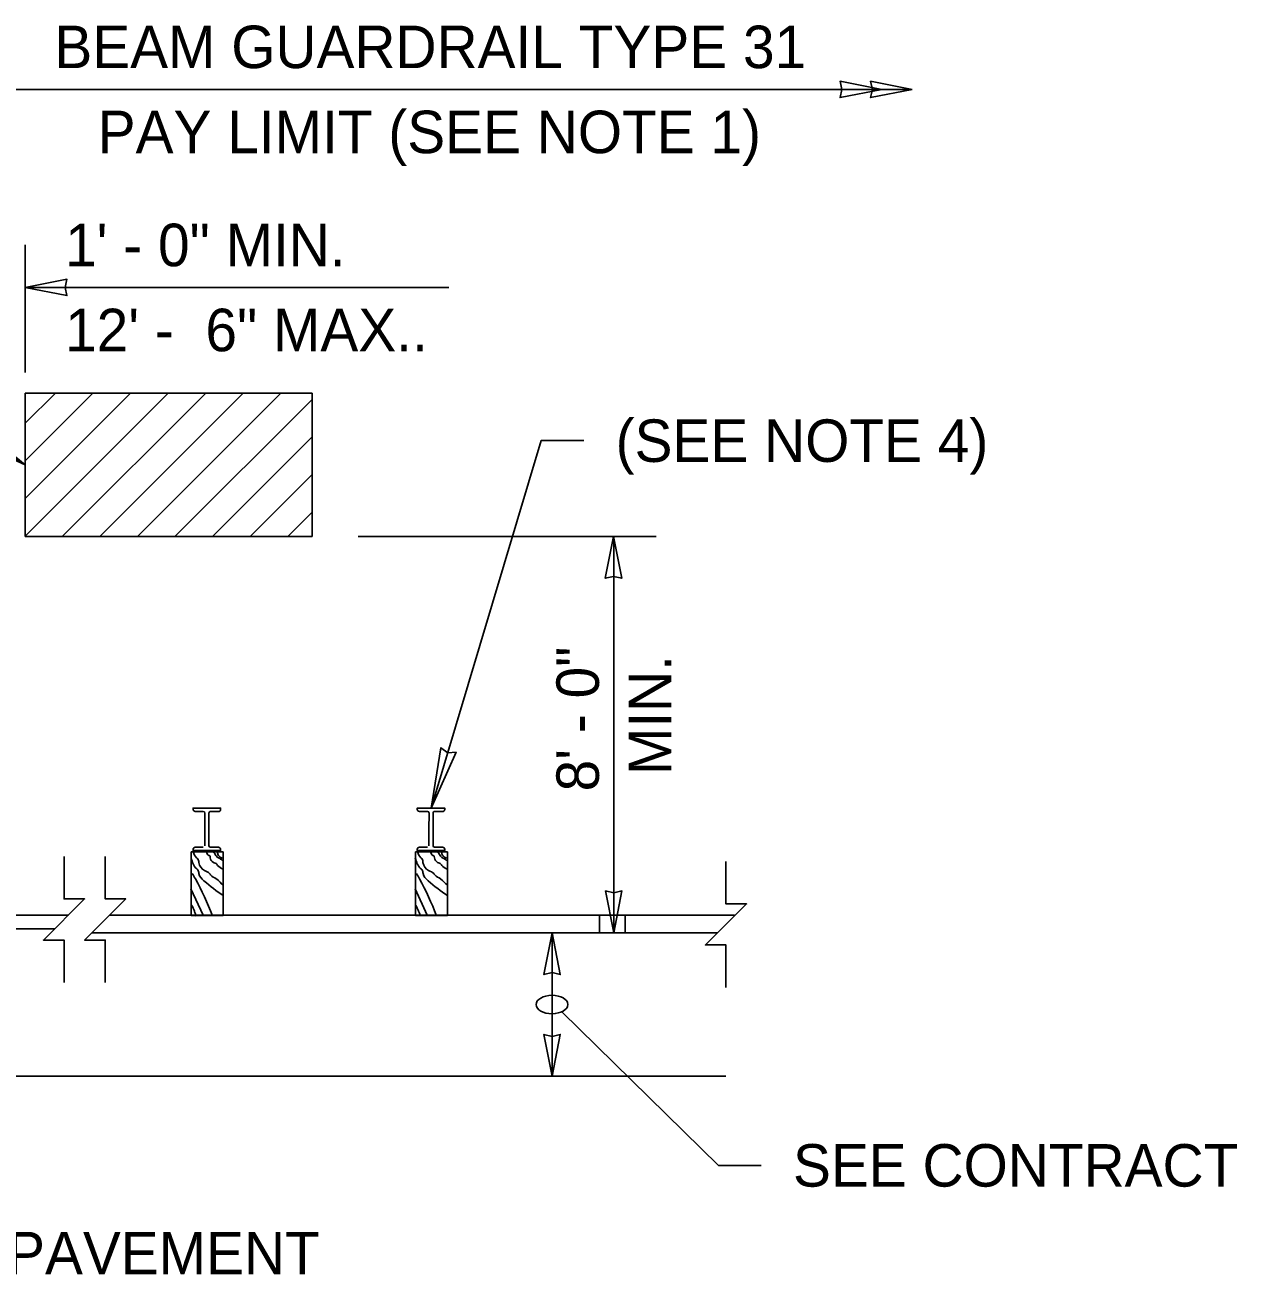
# Model space of a CAD drawing. Extents: x 99862 to 103680, y 99470 to 102076.
# Drawn here: x 100949.2 to 101405.4, y 100910.7 to 101381.1 of the extents above; entities that cross this region are included whole.
import ezdxf

# ---------------------------------------------------------------- set-up
doc = ezdxf.new("R2010")
doc.units = 0
for name, color, linetype in [('Level 1', 7, 'Continuous'), ('Level 10', 7, 'Continuous'), ('Level 13', 7, 'Continuous'), ('Level 15', 7, 'Continuous'), ('Level 17', 7, 'Continuous'), ('Level 2', 7, 'Continuous'), ('Level 20', 7, 'Continuous'), ('Level 21', 7, 'Continuous'), ('Level 4', 7, 'Continuous'), ('Level 9', 7, 'Continuous')]:
    doc.layers.add(name, color=color, linetype=linetype)

msp = doc.modelspace()

# ---------------------------------------------------------------- linework, layer by layer
at = {"layer": 'Level 1'}
for p, q in [((101216.27, 101046.07), (100981.02, 101046.07)), ((101165.38, 101046.07), (101165.38, 101039.46)), ((101175.15, 101046.07), (101175.15, 101039.46)), ((101209.66, 101039.46), (100974.41, 101039.46))]:
    msp.add_line(p, q, dxfattribs=at)
at = {"layer": 'Level 10'}
for p, q in [((101011.78, 101069.95), (101023.78, 101069.95)), ((101011.78, 101069.95), (101011.78, 101045.95)), ((101023.78, 101045.95), (101023.78, 101069.95)), ((101096.16, 101069.95), (101108.16, 101069.95)), ((101096.16, 101069.95), (101096.16, 101045.95)), ((101108.16, 101045.95), (101108.16, 101069.95)), ((101011.78, 101045.95), (101023.78, 101045.95)), ((101016.84, 101045.86), (101016.84, 101045.95)), ((101016.84, 101045.86), (101016.84, 101045.95)), ((101018.72, 101045.95), (101018.72, 101045.86)), ((101018.72, 101045.95), (101018.72, 101045.86)), ((101096.16, 101045.95), (101108.16, 101045.95)), ((101101.22, 101045.86), (101101.22, 101045.95)), ((101101.22, 101045.86), (101101.22, 101045.95)), ((101103.09, 101045.95), (101103.09, 101045.86)), ((101103.09, 101045.95), (101103.09, 101045.86))]:
    msp.add_line(p, q, dxfattribs=at)
at = {"layer": 'Level 13'}
for p, q in [((101011.66, 101056.04), (101016.25, 101046.03)), ((101096.03, 101056.04), (101100.63, 101046.03))]:
    msp.add_line(p, q, dxfattribs=at)
for points in [[(101012.54, 101069.94), (101013.81, 101067.66), (101014.26, 101067.25), (101014.62, 101065.86), (101016.74, 101062.84), (101018.65, 101061.75), (101019.06, 101061.21), (101021.2, 101059.76), (101021.38, 101059.62), (101023.8, 101057.34)], [(101017.51, 101069.94), (101018.32, 101068.58), (101018.72, 101068.42), (101018.89, 101067.7), (101020.13, 101065.93), (101021.37, 101065.28), (101021.7, 101064.84), (101023.76, 101063.43)], [(101020.2, 101069.95), (101020.62, 101069.26), (101021.52, 101067.98), (101022.51, 101067.38), (101023.68, 101066.65)], [(101021.62, 101069.92), (101021.97, 101068.6), (101023.68, 101067.48)], [(101096.91, 101069.94), (101098.19, 101067.66), (101098.64, 101067.25), (101098.99, 101065.86), (101101.12, 101062.84), (101103.03, 101061.75), (101103.44, 101061.21), (101105.57, 101059.76), (101105.75, 101059.62), (101108.17, 101057.34)], [(101101.88, 101069.94), (101102.7, 101068.58), (101103.1, 101068.42), (101103.27, 101067.7), (101104.51, 101065.93), (101105.75, 101065.28), (101106.07, 101064.84), (101108.13, 101063.43)], [(101104.58, 101069.95), (101104.99, 101069.26), (101105.9, 101067.98), (101106.89, 101067.38), (101108.06, 101066.65)], [(101105.99, 101069.92), (101106.35, 101068.6), (101108.06, 101067.48)], [(101011.72, 101067.68), (101013.82, 101063.54), (101014.27, 101063.13), (101014.63, 101061.74), (101016.57, 101059.02), (101023.78, 101053.43)], [(101096.1, 101067.68), (101098.2, 101063.54), (101098.65, 101063.13), (101099, 101061.74), (101100.95, 101059.02), (101108.16, 101053.43)], [(101012.18, 101061.82), (101013.33, 101059.81), (101019.75, 101045.89)], [(101096.56, 101061.82), (101097.71, 101059.81), (101104.12, 101045.89)], [(101011.76, 101050.11), (101011.91, 101049.85), (101012.06, 101049.59), (101012.33, 101049.05), (101012.82, 101047.94), (101013.28, 101046.81), (101013.51, 101046.24), (101013.75, 101045.69)], [(101096.14, 101050.11), (101096.29, 101049.85), (101096.43, 101049.59), (101096.71, 101049.05), (101097.19, 101047.94), (101097.65, 101046.81), (101097.88, 101046.24), (101098.12, 101045.69)]]:
    msp.add_spline(points, degree=3, dxfattribs=at)
at = {"layer": 'Level 15'}
for p, q in [((100949.27, 101215.58), (100837.28, 101282.31)), ((101102.03, 101086.38), (101143.51, 101224.66)), ((101159.51, 101224.66), (101143.51, 101224.66)), ((101170.81, 101039.46), (101170.81, 101188.58)), ((101147.56, 100985.46), (101147.56, 101039.46)), ((101210.25, 100951.93), (101151.24, 101009.72)), ((101226.25, 100951.93), (101210.25, 100951.93))]:
    msp.add_line(p, q, dxfattribs=at)
for points in [[(100949.27, 101215.58), (100931.42, 101230.12), (100930.75, 101227.03), (100928.28, 101225.04)], [(101102.03, 101086.38), (101105.73, 101109.1), (101108.29, 101107.23), (101111.45, 101107.39)], [(101170.81, 101039.46), (101167.72, 101055.19), (101170.81, 101054.46), (101173.89, 101055.19)], [(101147.56, 101039.46), (101144.48, 101023.74), (101147.56, 101024.47), (101150.65, 101023.74)], [(101147.56, 100985.46), (101144.48, 101001.19), (101147.56, 101000.46), (101150.65, 101001.19)]]:
    msp.add_lwpolyline(points, close=True, dxfattribs=at)
for points in [[(100963.91, 101068.19), (100963.91, 101052.19), (100971.65, 101052.19), (100956.16, 101036.7), (100963.91, 101036.7), (100963.91, 101020.7)], [(100979.39, 101068.19), (100979.39, 101052.19), (100987.14, 101052.19), (100971.65, 101036.7), (100979.39, 101036.7), (100979.39, 101020.7)], [(101213.04, 101066.35), (101213.04, 101050.35), (101220.79, 101050.35), (101205.3, 101034.87), (101213.04, 101034.87), (101213.04, 101018.87)]]:
    msp.add_lwpolyline(points, dxfattribs=at)
msp.add_ellipse((101147.56, 101012.46), major_axis=(6, 0.02), ratio=0.57735, dxfattribs=at)
at = {"layer": 'Level 17'}
for p, q in [((100949.27, 101188.58), (100949.27, 101242.58)), ((101057.27, 101242.58), (100949.27, 101242.58)), ((100949.27, 101231.21), (100960.65, 101242.58)), ((100949.27, 101217.07), (100974.79, 101242.58)), ((100949.27, 101202.92), (100988.93, 101242.58)), ((100949.27, 101188.78), (101003.07, 101242.58)), ((100963.21, 101188.58), (101017.21, 101242.58)), ((100977.36, 101188.58), (101031.36, 101242.58)), ((100991.5, 101188.58), (101045.5, 101242.58)), ((101057.27, 101188.58), (101057.27, 101242.58)), ((101005.64, 101188.58), (101057.27, 101240.21)), ((101019.78, 101188.58), (101057.27, 101226.07)), ((101033.92, 101188.58), (101057.27, 101211.93)), ((101048.07, 101188.58), (101057.27, 101197.79)), ((101057.27, 101188.58), (100949.27, 101188.58))]:
    msp.add_line(p, q, dxfattribs=at)
at = {"layer": 'Level 2'}
for p, q in [((100965.53, 101046.07), (100735.54, 101046.07)), ((100960.44, 101040.98), (100754.27, 101040.98))]:
    msp.add_line(p, q, dxfattribs=at)
at = {"layer": 'Level 20'}
for p, q in [((100933.41, 101356.85), (101283.16, 101356.85)), ((100949.27, 101250.31), (100949.27, 101298.31)), ((100949.27, 101282.31), (101108.71, 101282.31)), ((101074.61, 101188.58), (101186.7, 101188.58))]:
    msp.add_line(p, q, dxfattribs=at)
for points in [[(101271.67, 101356.85), (101255.95, 101353.77), (101256.67, 101356.85), (101255.95, 101359.94)], [(101283.16, 101356.85), (101267.44, 101353.77), (101268.17, 101356.85), (101267.44, 101359.94)], [(100949.27, 101282.31), (100965, 101279.23), (100964.27, 101282.31), (100965, 101285.39)], [(101170.7, 101188.58), (101167.62, 101172.86), (101170.7, 101173.58), (101173.79, 101172.86)]]:
    msp.add_lwpolyline(points, close=True, dxfattribs=at)
at = {"layer": 'Level 21'}
msp.add_line((101213.04, 100985.46), (100717.77, 100985.46), dxfattribs=at)
at = {"layer": 'Level 4'}
msp.add_line((101013.28, 101045.95), (101022.28, 101045.95), dxfattribs=at)
at = {"layer": 'Level 9'}
for p, q in [((101016.88, 101084.52), (101016.88, 101078.38)), ((101018.42, 101078.38), (101018.43, 101084.51)), ((101101.26, 101084.52), (101101.25, 101078.38)), ((101102.79, 101078.38), (101102.8, 101084.51)), ((101016.88, 101078.38), (101016.87, 101072.24)), ((101018.41, 101072.24), (101018.42, 101078.38)), ((101101.25, 101078.38), (101101.24, 101072.24)), ((101102.79, 101072.24), (101102.79, 101078.38))]:
    msp.add_line(p, q, dxfattribs=at)
for points in [[(101017.66, 101086.38), (101012.49, 101086.38), (101012.49, 101085.9)], [(101013.27, 101085.11), (101016.29, 101085.11)], [(101022.83, 101085.89), (101022.83, 101086.37), (101017.66, 101086.38)], [(101019.02, 101085.1), (101022.04, 101085.1)], [(101102.03, 101086.38), (101096.86, 101086.38), (101096.86, 101085.9)], [(101097.65, 101085.11), (101100.67, 101085.11)], [(101107.2, 101085.89), (101107.2, 101086.37), (101102.03, 101086.38)], [(101103.39, 101085.1), (101106.41, 101085.1)], [(101012.47, 101070.87), (101012.47, 101070.38), (101017.64, 101070.38)], [(101016.28, 101071.65), (101013.26, 101071.65)], [(101017.64, 101070.38), (101022.81, 101070.37), (101022.81, 101070.86)], [(101022.02, 101071.64), (101019, 101071.65)], [(101096.84, 101070.87), (101096.84, 101070.38), (101102.01, 101070.38)], [(101100.65, 101071.65), (101097.63, 101071.65)], [(101102.01, 101070.38), (101107.18, 101070.37), (101107.18, 101070.86)], [(101106.39, 101071.64), (101103.38, 101071.65)]]:
    msp.add_lwpolyline(points, dxfattribs=at)
for centre, radius, start, end in [((101013.28, 101085.9), 0.788, 179.9273, 269.9273), ((101016.29, 101084.52), 0.591, 359.9273, 89.9273), ((101019.02, 101084.51), 0.591, 89.9273, 179.9273), ((101022.04, 101085.89), 0.788, 269.9273, 359.9273), ((101097.65, 101085.9), 0.788, 179.9273, 269.9273), ((101100.67, 101084.52), 0.591, 359.9273, 89.9273), ((101103.39, 101084.51), 0.591, 89.9273, 179.9273), ((101106.41, 101085.89), 0.788, 269.9273, 359.9273), ((101013.26, 101070.87), 0.788, 89.9273, 179.9478), ((101019, 101072.24), 0.591, 179.9273, 269.9273), ((101022.02, 101070.86), 0.788, 359.9478, 89.9273), ((101097.63, 101070.87), 0.788, 89.9273, 179.9478), ((101103.38, 101072.24), 0.591, 179.9273, 269.9273), ((101106.39, 101070.86), 0.788, 359.9478, 89.9273)]:
    msp.add_arc(centre, radius, start, end, dxfattribs=at)

# ---------------------------------------------------------------- texts
at = {"layer": 'Level 15'}
for s, p in [('8\' - 0" ', (101165.21, 101092.66)), ('MIN.', (101192.41, 101098.82))]:
    msp.add_text(s, height=16, rotation=90, dxfattribs=at).set_placement(p)
at = {"layer": 'Level 20'}
for s, p in [('BEAM GUARDRAIL TYPE 31', (100960.25, 101364.85)), ('PAY LIMIT (SEE NOTE 1)', (100976.56, 101332.85)), ('1\' - 0" MIN.', (100964.27, 101290.31)), ('12\' -  6" MAX..', (100964.27, 101258.31)), ('SEE CONTRACT', (101238.25, 100943.93)), ('EDGE OF PAVEMENT', (100840.22, 100910.9))]:
    msp.add_text(s, height=16, dxfattribs=at).set_placement(p)
msp.add_text('(SEE NOTE 4)', height=16, rotation=360, dxfattribs=at).set_placement((101171.5, 101216.66))

doc.saveas('drawing.dxf')
